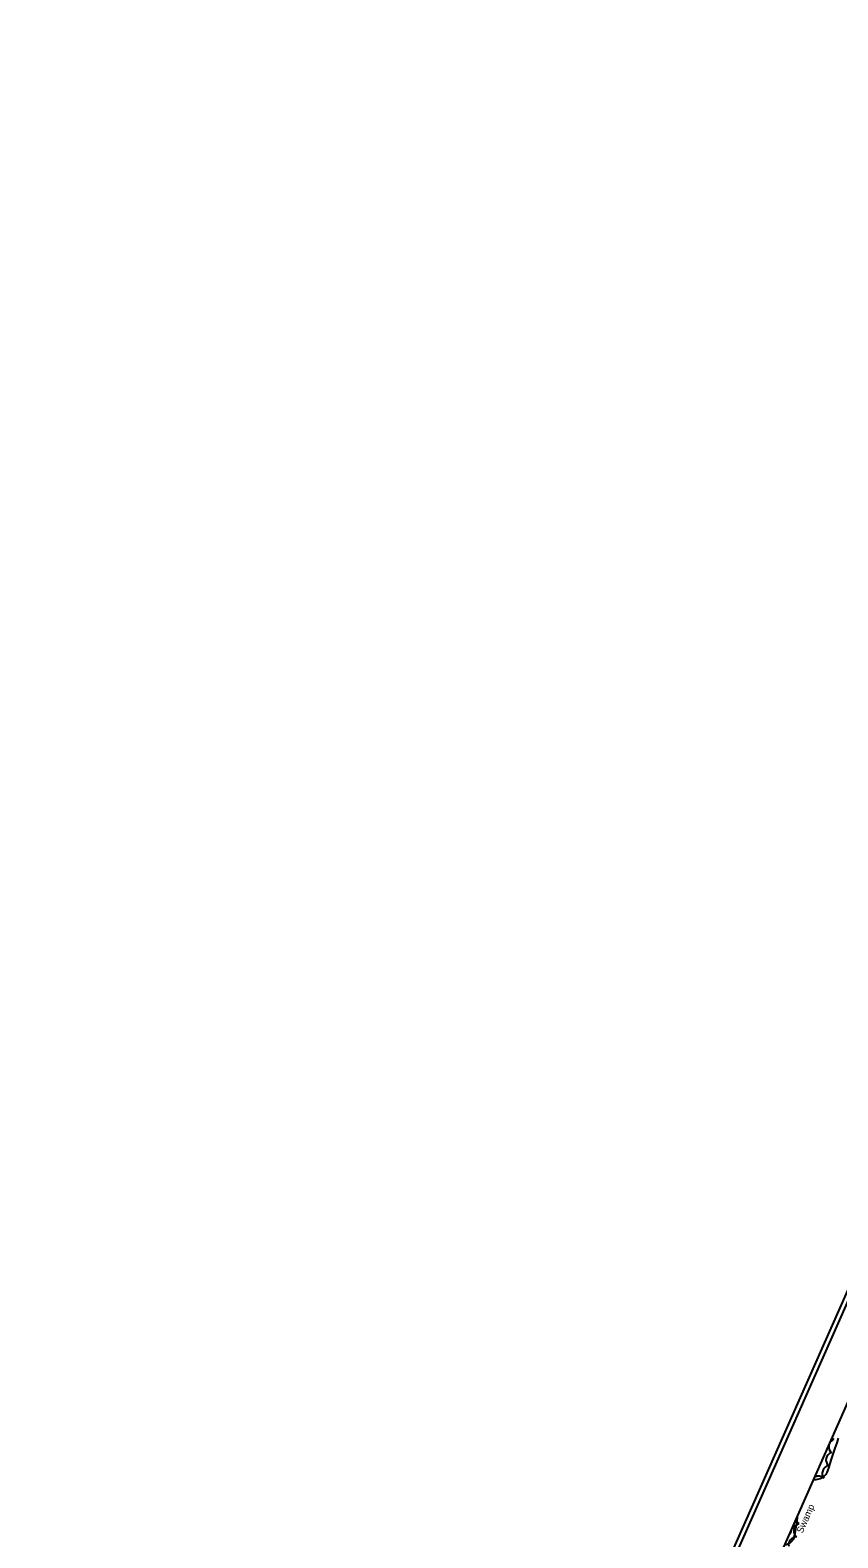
# Model space of a CAD drawing. Extents: x 287698 to 290158, y 5234163 to 5237182.
# Drawn here: x 287698 to 288054, y 5235484 to 5236149 of the extents above; entities that cross this region are included whole.
import ezdxf

# ---------------------------------------------------------------- set-up
doc = ezdxf.new("R2010")
doc.units = 0
for name, color, linetype in [('Niveau 4', 7, 'Continuous'), ('Niveau 44', 7, 'Continuous'), ('Niveau 60', 7, 'Continuous'), ('Niveau 7', 7, 'Continuous')]:
    doc.layers.add(name, color=color, linetype=linetype)

msp = doc.modelspace()

# ---------------------------------------------------------------- linework, layer by layer
at = {"layer": 'Niveau 4'}
msp.add_lwpolyline([(288033.02, 5235485.8), (288033.4, 5235486.17), (288033.87, 5235487.12), (288033.98, 5235487.72), (288034.03, 5235488.07)], dxfattribs=at)
at = {"layer": 'Niveau 44'}
msp.add_arc((288052.54, 5235518.71), 3.37, 106.63194, 228.5001, dxfattribs=at)
for centre, major_axis, ratio, start_param, end_param in [((288053.74, 5235524.54), (1.14, -3.19), 0.999994, 4.229875, 5.245498), ((288053.74, 5235524.54), (1.14, -3.19), 0.999994, 3.114747, 3.673762), ((288054.44, 5235530.72), (-3.47, 0), 0.990278, 0.741929, 1.038775), ((288045.87, 5235508.25), (-3.2, -1.01), 0.984455, 3.635741, 4.920077), ((288050.65, 5235512.89), (-1.18, -3.15), 0.929808, 3.635679, 5.789099), ((288038.11, 5235487.49), (-0.77, -3.27), 0.928179, 3.696616, 5.855341), ((288039.16, 5235493.39), (-3.18, 1.19), 0.999927, 0.667101, 1.302012), ((288035.93, 5235481.53), (-2.08, -2.64), 0.934682, 3.774173, 5.614865)]:
    msp.add_ellipse(centre, major_axis=major_axis, ratio=ratio, start_param=start_param, end_param=end_param, dxfattribs=at)
at = {"layer": 'Niveau 60'}
for points in [[(289088.15, 5234163.34), (287698.12, 5234778.71), (288762.01, 5237181.96), (290152.07, 5236566.6), (289088.15, 5234163.34)], [(289087.13, 5234165.98), (287700.76, 5234779.73), (288763.06, 5237179.33), (290149.43, 5236565.58), (289087.13, 5234165.98)]]:
    msp.add_lwpolyline(points, dxfattribs=at)
msp.add_lwpolyline([(289077.96, 5234189.73), (287724.51, 5234788.9), (288562.53, 5236681.9), (289915.99, 5236082.74)], close=True, dxfattribs=at)
at = {"layer": 'Niveau 7'}
for points in [[(288054.57, 5235528.28), (288053.89, 5235526.2), (288053.07, 5235523.86), (288052.27, 5235521.33), (288051.5, 5235519.08), (288050.92, 5235517.08), (288050.31, 5235515.09), (288049.53, 5235513.14), (288049.07, 5235512.36), (288048.58, 5235511.73), (288047.8, 5235511), (288047.18, 5235510.65), (288046.6, 5235510.45), (288044.77, 5235509.99), (288043.65, 5235509.8)], [(288036.45, 5235493.54), (288036.26, 5235491.57), (288035.94, 5235489.21), (288035.58, 5235487.18), (288034.97, 5235484.37), (288034.68, 5235483.7), (288034.26, 5235483.04), (288033.73, 5235482.45), (288033.11, 5235481.93), (288032.38, 5235481.56), (288031.56, 5235481.34), (288031.04, 5235481.32)]]:
    msp.add_lwpolyline(points, dxfattribs=at)

# ---------------------------------------------------------------- texts
msp.add_text('Swamp', height=3, rotation=66.12117, dxfattribs=at).set_placement((288038.8, 5235486.17))

doc.saveas('drawing.dxf')
